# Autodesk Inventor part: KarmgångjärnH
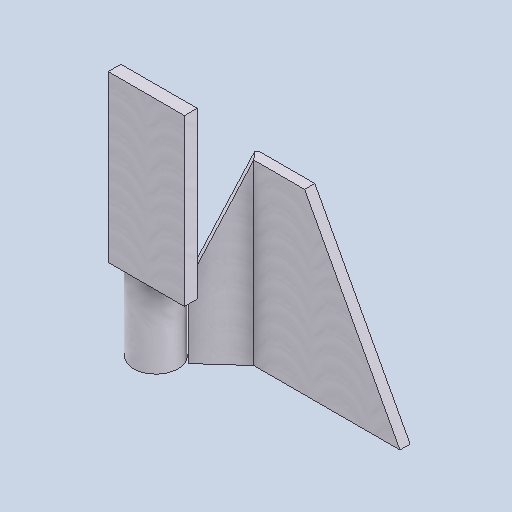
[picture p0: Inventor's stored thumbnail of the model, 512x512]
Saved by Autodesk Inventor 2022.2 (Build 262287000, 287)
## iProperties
Created: 2019-06
Part Number: KarmgångjärnH
Material: Aluminum 6061, Welded
Document SubType Name: Modeling
Designer: cl
Density: 2.7 g/cm^3
Appearance: Weld - Aluminum
Author: cl
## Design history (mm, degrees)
sketch "Sketch1"
  geometry: L1 (0, 8)-(115, 8); L2 (118.071, 0)-(0, 0); L3 (0, 0)-(0, 8); L4 (115, 8)-(142.016, 32.325); L5 (115, 8)-(126.561, 8); L6 (118.071, 0)-(147.369, 26.38); L7 (142.016, 32.325)-(147.369, 26.38); C1 r 17.5 at (160, 40); 2 further points
  constraints: 14 end point, 2 coincident, 2 horizontal, 2 parallel, 1 centre point, 1 vertical
  dimensions: "d0" = 35 diameter of C1; "d1" = 40 vertical distance of point (0, 0) C1.centre; "d2" = 160 horizontal distance of point (0, 0) C1.centre; "d3" = 42 deg angle of L5 L4; "d4" = 8 distance between parallel lines of L4 L6; "d5" = 8 distance between parallel lines of L1 L2; "d6" = 115 horizontal distance of point (0, 0) L1.end; "d7" = 1 distance edge to line of C1 L7; "d8" = 90 deg angle of L4 L7; "d10" = 27.76238 distance from line of L5.end L7
extrude "Extrusion1" new body sketch "Sketch1" distance "d11" = 140; taper "d12" = 0 deg
thicken "Thicken1" dims "d13" = 10, "d14" = 80
chamfer "Chamfer1" distance "d15" = 140; stored, may be unused: second distance "d16" = 75, angle "d17" = 45 deg
sketch "Sketch2"
  geometry: L1 (-36.354, 140)-(-66.079, 140) reference; L2 (-36.354, 140)-(0, 56); L3 (0, 0)-(0, 140) reference; L4 (0, 140)-(-36.354, 140) reference; L5 (0, 56)-(0, 140); L6 (0, 140)-(-36.354, 140); 1 further point
  constraints: 6 end point, 1 perpendicular, 1 point on line, 1 vertical
  dimensions: "d18" = 56 distance of L3.start L2.end
extrude "Extrusion2" cut sketch "Sketch2" extent not by distance; stored distance "d19" = 29.794; taper "d20" = 0 deg
workplane "Work Plane1"
sketch "Sketch3"
  geometry: L1 (-57.5, 200)-(2.5, 200); L2 (2.5, 200)-(2.5, 70); L3 (2.5, 70)-(-57.5, 70); L4 (-57.5, 70)-(-57.5, 200); L5 (-62.5, 130)-(-27.5, 130) reference; L6 (-27.5, 0)-(-62.5, 0) reference; 1 further point
  constraints: 8 end point, 2 parallel, 1 horizontal, 1 perpendicular
  dimensions: "d22" = 5 distance from line of L5.start L4; "d23" = 60 distance of L1.start L1.end; "d24" = 130 distance of L3.end L1.start; "d25" = 70 distance between parallel lines of L1 L5
extrude "Extrusion3" join sketch "Sketch3" distance "d26" = 10; taper "d27" = 0 deg
body "Solid1"
node "Projected Loop1"
other parameters: "d21" = 57
